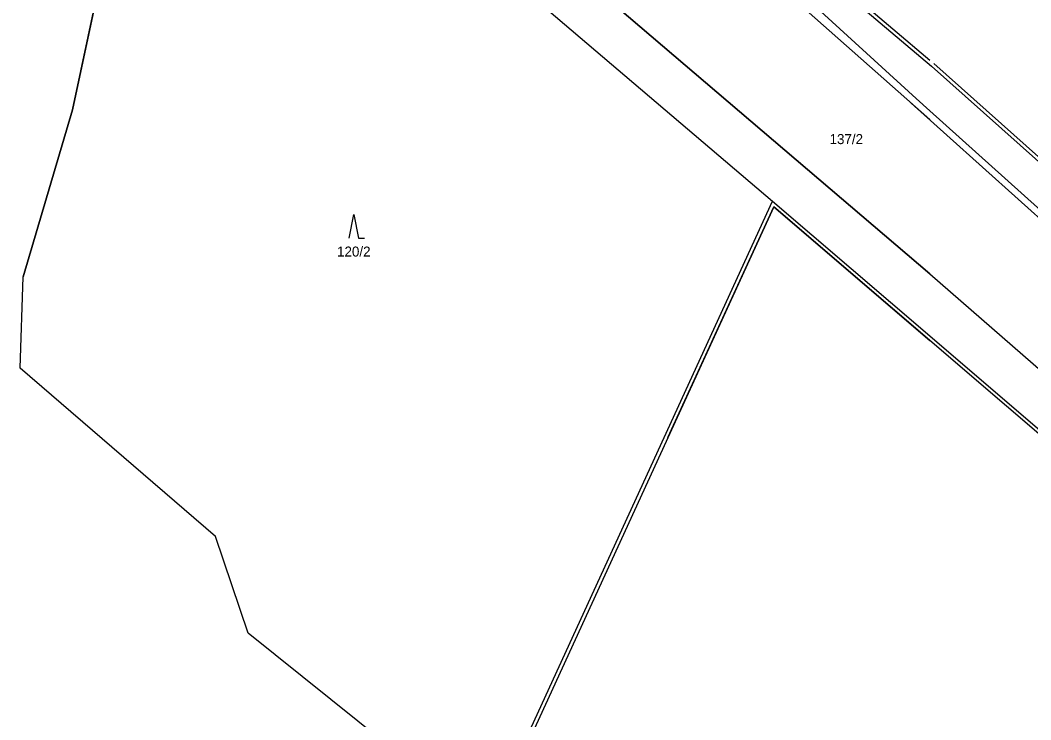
# Model space of a CAD drawing. Extents: x -792659 to -786947, y -1118170 to -1109641.
# Drawn here: x -789639.5 to -789553.7, y -1114376.9 to -1114317.5 of the extents above; entities that cross this region are included whole.
import ezdxf

# ---------------------------------------------------------------- set-up
doc = ezdxf.new("R2010")
doc.units = 0
doc.layers.add('1', color=7, linetype='Continuous')

# ---------------------------------------------------------------- blocks, each defined once
blk = doc.blocks.new('Z30801')
at = {"layer": '1'}
for p, q in [((-0.8, 0), (0, 4)), ((0, 4), (0.8, 0)), ((0.8, 0), (1.8, 0))]:
    blk.add_line(p, q, dxfattribs=at)

msp = doc.modelspace()

# ---------------------------------------------------------------- linework, layer by layer
at = {"layer": '1'}
for p, q in [((-789562.235, -1114339.028), (-789619.3, -1114290.36)), ((-789619.3, -1114290.36), (-789562.235, -1114339.028)), ((-789624.34, -1114291.37), (-789575.6, -1114332.86)), ((-789624.34, -1114291.37), (-789575.6, -1114332.86)), ((-789592.9, -1114298.82), (-789562.235, -1114325.922)), ((-789590.47, -1114299.37), (-789563.4, -1114324.15)), ((-789587.26, -1114300.1), (-789562.096, -1114321.394)), ((-789586.079, -1114300.705), (-789562.235, -1114320.883)), ((-789631.47, -1114308.38), (-789635.04, -1114325.1)), ((-789635.04, -1114325.1), (-789631.47, -1114308.38)), ((-789562.096, -1114321.394), (-789502.74, -1114374.33)), ((-789561.897, -1114321.17), (-789502.54, -1114374.106)), ((-789563.81, -1114324.53), (-789505.98, -1114376.61)), ((-789563.4, -1114324.15), (-789562.235, -1114325.197)), ((-789635.04, -1114325.1), (-789639.25, -1114339.29)), ((-789639.25, -1114339.29), (-789635.04, -1114325.1)), ((-789562.235, -1114325.197), (-789505.63, -1114376.09)), ((-789584.811, -1114352.945), (-789575.6, -1114332.86)), ((-789575.6, -1114332.86), (-789562.235, -1114344.307)), ((-789584.481, -1114352.945), (-789575.493, -1114333.346)), ((-789575.493, -1114333.346), (-789562.235, -1114344.701)), ((-789562.235, -1114339.028), (-789512.77, -1114382.14)), ((-789639.49, -1114347.05), (-789639.25, -1114339.29)), ((-789562.235, -1114344.307), (-789515.81, -1114384.07)), ((-789622.91, -1114361.34), (-789639.49, -1114347.05)), ((-789599.87, -1114385.78), (-789584.811, -1114352.945)), ((-789620.14, -1114369.54), (-789622.91, -1114361.34)), ((-789599.87, -1114385.78), (-789620.14, -1114369.54))]:
    msp.add_line(p, q, dxfattribs=at)
msp.add_lwpolyline([(-789442.498, -1114466.81), (-789454.803, -1114445.682), (-789466.417, -1114429.039), (-789481.082, -1114415.572), (-789516.008, -1114384.296), (-789575.493, -1114333.347), (-789576.457, -1114335.455), (-789599.597, -1114385.905), (-789602.987, -1114393.315), (-789604.587, -1114396.795)], dxfattribs=at)
msp.add_arc((-789628.904, -1114546.239), 255, 50.01412, 72.83771, dxfattribs=at)
msp.add_arc((-789628.904, -1114546.239), 255, 50.01412, 72.83771, dxfattribs=at)

# ---------------------------------------------------------------- block references
at = {"layer": '1', "xscale": 0.5, "yscale": 0.5}
msp.add_blockref('Z30801', (-789611.16, -1114336), dxfattribs=at)

# ---------------------------------------------------------------- texts
at = {"layer": '1'}
for s, p in [('137/2', (-789570.75, -1114328.02)), ('120/2', (-789612.58, -1114337.57))]:
    msp.add_text(s, height=0.85, dxfattribs=at).set_placement(p)

doc.saveas('drawing.dxf')
